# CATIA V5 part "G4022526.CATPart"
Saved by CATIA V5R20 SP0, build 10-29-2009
Part number: G4022526
Revision: 5
Definition: design
Nomenclature: G4022526
Source: made
Description: NOT SPECIFIED
Bounding box of the stored display mesh (mm): x -18 to 26, y -17.817 to 17.817, z -18 to 18
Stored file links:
  C:\Users\Raffaele\Desktop\3D X SITO CF\BOLEX\26-BUSH REF 402\G4022526.CATPart
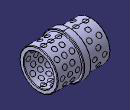
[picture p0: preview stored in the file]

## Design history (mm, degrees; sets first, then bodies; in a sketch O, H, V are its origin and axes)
Body1 "MANIFOLD_SOLID_BREP #9397" (main body)
  Solid1: solid without history
Body2 "MANIFOLD_SOLID_BREP #9546"
  Solid2: solid without history
Body3 "MANIFOLD_SOLID_BREP #9695"
  Solid3: solid without history
Body4 "MANIFOLD_SOLID_BREP #9844"
  Solid4: solid without history
Body5 "MANIFOLD_SOLID_BREP #9993"
  Solid5: solid without history
Body6 "MANIFOLD_SOLID_BREP #10142"
  Solid6: solid without history
Body7 "MANIFOLD_SOLID_BREP #10291"
  Solid7: solid without history
Body8 "MANIFOLD_SOLID_BREP #10440"
  Solid8: solid without history
Body9 "MANIFOLD_SOLID_BREP #10589"
  Solid9: solid without history
Body10 "MANIFOLD_SOLID_BREP #10738"
  Solid10: solid without history
Body11 "MANIFOLD_SOLID_BREP #10887"
  Solid11: solid without history
Body12 "MANIFOLD_SOLID_BREP #11036"
  Solid12: solid without history
Body13 "MANIFOLD_SOLID_BREP #11185"
  Solid13: solid without history
Body14 "MANIFOLD_SOLID_BREP #11334"
  Solid14: solid without history
Body15 "MANIFOLD_SOLID_BREP #11483"
  Solid15: solid without history
Body16 "MANIFOLD_SOLID_BREP #11632"
  Solid16: solid without history
Body17 "MANIFOLD_SOLID_BREP #11781"
  Solid17: solid without history
Body18 "MANIFOLD_SOLID_BREP #11930"
  Solid18: solid without history
Body19 "MANIFOLD_SOLID_BREP #12079"
  Solid19: solid without history
Body20 "MANIFOLD_SOLID_BREP #12230"
  Solid20: solid without history
Body21 "MANIFOLD_SOLID_BREP #12379"
  Solid21: solid without history
Body22 "MANIFOLD_SOLID_BREP #12528"
  Solid22: solid without history
Body23 "MANIFOLD_SOLID_BREP #12679"
  Solid23: solid without history
Body24 "MANIFOLD_SOLID_BREP #12828"
  Solid24: solid without history
Body25 "MANIFOLD_SOLID_BREP #12977"
  Solid25: solid without history
Body26 "MANIFOLD_SOLID_BREP #13126"
  Solid26: solid without history
Body27 "MANIFOLD_SOLID_BREP #13275"
  Solid27: solid without history
Body28 "MANIFOLD_SOLID_BREP #13424"
  Solid28: solid without history
Body29 "MANIFOLD_SOLID_BREP #13573"
  Solid29: solid without history
Body30 "MANIFOLD_SOLID_BREP #13722"
  Solid30: solid without history
Body31 "MANIFOLD_SOLID_BREP #13871"
  Solid31: solid without history
Body32 "MANIFOLD_SOLID_BREP #14020"
  Solid32: solid without history
Body33 "MANIFOLD_SOLID_BREP #14169"
  Solid33: solid without history
Body34 "MANIFOLD_SOLID_BREP #14318"
  Solid34: solid without history
Body35 "MANIFOLD_SOLID_BREP #14467"
  Solid35: solid without history
Body36 "MANIFOLD_SOLID_BREP #14618"
  Solid36: solid without history
Body37 "MANIFOLD_SOLID_BREP #14767"
  Solid37: solid without history
Body38 "MANIFOLD_SOLID_BREP #14916"
  Solid38: solid without history
Body39 "MANIFOLD_SOLID_BREP #15067"
  Solid39: solid without history
Body40 "MANIFOLD_SOLID_BREP #15216"
  Solid40: solid without history
Body41 "MANIFOLD_SOLID_BREP #15365"
  Solid41: solid without history
Body42 "MANIFOLD_SOLID_BREP #15514"
  Solid42: solid without history
Body43 "MANIFOLD_SOLID_BREP #15663"
  Solid43: solid without history
Body44 "MANIFOLD_SOLID_BREP #15812"
  Solid44: solid without history
Body45 "MANIFOLD_SOLID_BREP #15961"
  Solid45: solid without history
Body46 "MANIFOLD_SOLID_BREP #16110"
  Solid46: solid without history
Body47 "MANIFOLD_SOLID_BREP #16259"
  Solid47: solid without history
Body48 "MANIFOLD_SOLID_BREP #16408"
  Solid48: solid without history
Body49 "MANIFOLD_SOLID_BREP #16557"
  Solid49: solid without history
Body50 "MANIFOLD_SOLID_BREP #16706"
  Solid50: solid without history
Body51 "MANIFOLD_SOLID_BREP #16855"
  Solid51: solid without history
Body52 "MANIFOLD_SOLID_BREP #17004"
  Solid52: solid without history
Body53 "MANIFOLD_SOLID_BREP #17153"
  Solid53: solid without history
Body54 "MANIFOLD_SOLID_BREP #17302"
  Solid54: solid without history
Body55 "MANIFOLD_SOLID_BREP #17451"
  Solid55: solid without history
Body56 "MANIFOLD_SOLID_BREP #17600"
  Solid56: solid without history
Body57 "MANIFOLD_SOLID_BREP #17749"
  Solid57: solid without history
Body58 "MANIFOLD_SOLID_BREP #17898"
  Solid58: solid without history
Body59 "MANIFOLD_SOLID_BREP #18047"
  Solid59: solid without history
Body60 "MANIFOLD_SOLID_BREP #18198"
  Solid60: solid without history
Body61 "MANIFOLD_SOLID_BREP #18347"
  Solid61: solid without history
Body62 "MANIFOLD_SOLID_BREP #18496"
  Solid62: solid without history
Body63 "MANIFOLD_SOLID_BREP #18647"
  Solid63: solid without history
Body64 "MANIFOLD_SOLID_BREP #18796"
  Solid64: solid without history
Body65 "MANIFOLD_SOLID_BREP #18945"
  Solid65: solid without history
